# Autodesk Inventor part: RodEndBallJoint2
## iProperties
Author: Administrator
Shininess: 20.0
PropertySet Name: _Private Model Information
Created: 2001-01
Part Number: RodEndBallJoint2
Document SubType Name: Modeling
Designer: Administrator
Control State: 0
Master: False
Checked Out: False
PropertySet Name: Design Tracking Control
Density: 0.0
Volumn: 0.0
Area: 0.0
PropertySet Name: Model Information
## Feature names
1. Revolution1
2. Revolution2
3. Revolution3
4. Extrusion1
5. Extrusion2
6. Revolution4
